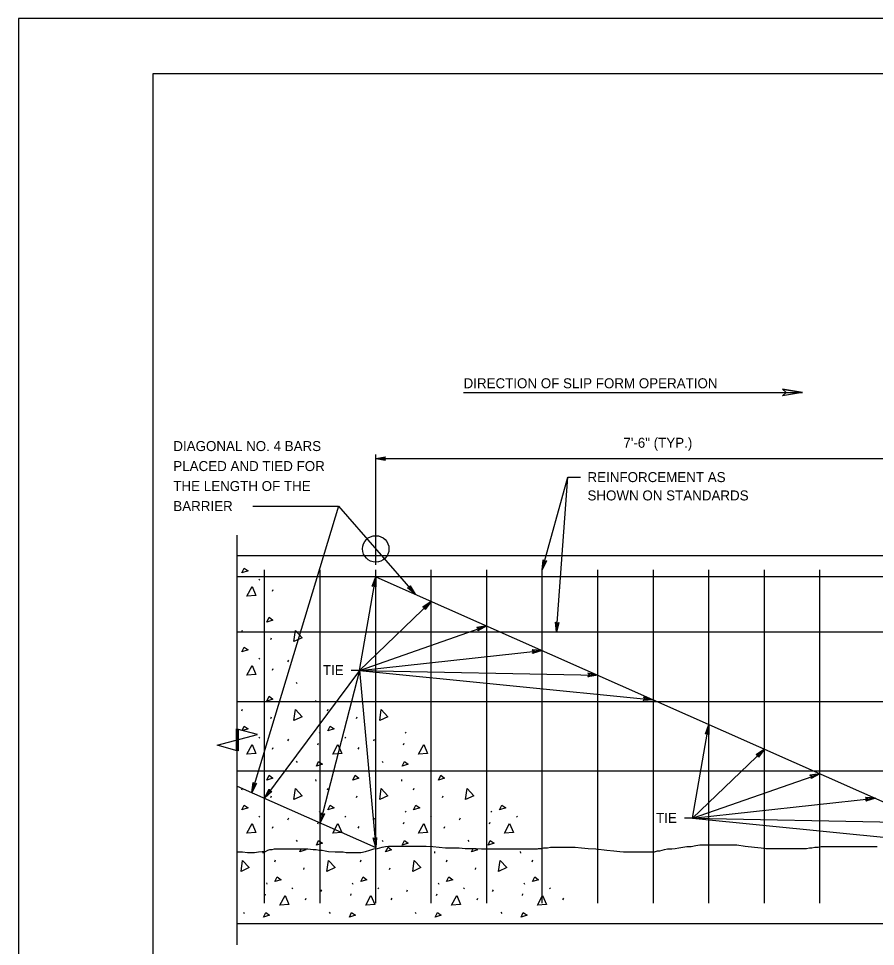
# Model space of a CAD drawing. Extents: x -113.6 to -105.1, y -201.8 to -190.8.
# Drawn here: x -113.61 to -108.47, y -196.35 to -190.78 of the extents above; entities that cross this region are included whole.
import ezdxf

# ---------------------------------------------------------------- set-up
doc = ezdxf.new("R2010")
doc.units = 0
for name, color, linetype in [('ANNO-DIMS', 7, 'Continuous'), ('ANNO-TEXT', 7, 'Continuous'), ('ANNO-WOUT', 7, 'Continuous'), ('BORD-LINE', 7, 'Continuous'), ('DETL-PATT', 7, 'Continuous'), ('Level 10', 7, 'Continuous'), ('Level 12', 7, 'Continuous'), ('SUBS-FOOT_P', 7, 'Continuous'), ('SUPR-PARA_P', 7, 'Continuous'), ('SUPR-RFRC', 7, 'Continuous'), ('USER-CLIP', 7, 'Continuous')]:
    doc.layers.add(name, color=color, linetype=linetype)

msp = doc.modelspace()

# ---------------------------------------------------------------- linework, layer by layer
at = {"layer": 'ANNO-DIMS'}
msp.add_lwpolyline([(-112.302, -195.1718), (-112.4227, -195.1394), (-112.1812, -195.0747), (-112.302, -195.0424)], dxfattribs=at)
msp.add_lwpolyline([(-112.2971, -195.1729), (-112.3062, -195.1706), (-112.3062, -195.0412), (-112.2971, -195.0437)], close=True, dxfattribs=at)
at = {"layer": 'ANNO-TEXT'}
msp.add_line((-112.302, -196.3362), (-112.302, -193.8779), dxfattribs=at)
at = {"layer": 'ANNO-WOUT'}
msp.add_circle((-111.4705, -193.9608), 0.0795, dxfattribs=at)
at = {"layer": 'BORD-LINE'}
msp.add_lwpolyline([(-112.8058, -191.1077), (-105.4316, -191.1077), (-105.4316, -201.4608), (-112.8058, -201.4608)], close=True, dxfattribs=at)
at = {"layer": 'DETL-PATT'}
for p, q in [((-112.1717, -194.1419), (-112.1665, -194.1483)), ((-112.0905, -194.214), (-112.0854, -194.2037)), ((-112.2747, -194.4588), (-112.2709, -194.4485)), ((-112.1008, -194.5051), (-112.0969, -194.4948)), ((-112.1717, -194.6159), (-112.1665, -194.6224)), ((-111.9978, -194.6378), (-111.9926, -194.6275)), ((-112.0905, -194.6881), (-112.0854, -194.6778)), ((-111.9475, -194.7615), (-111.9424, -194.7692)), ((-111.8316, -194.871), (-111.8303, -194.8813)), ((-112.2747, -194.9328), (-112.2709, -194.9225)), ((-111.7594, -194.9328), (-111.7556, -194.9225)), ((-112.1008, -194.9792), (-112.0969, -194.9689)), ((-111.5855, -194.9792), (-111.5816, -194.9689)), ((-111.8097, -195.0604), (-111.8058, -195.0668)), ((-111.2944, -195.0604), (-111.2905, -195.0668)), ((-112.1717, -195.09), (-112.1665, -195.0965)), ((-111.9978, -195.1119), (-111.9926, -195.1016)), ((-111.8187, -195.1364), (-111.8148, -195.1261)), ((-111.6564, -195.09), (-111.6512, -195.0965)), ((-111.4825, -195.1119), (-111.4773, -195.1016)), ((-111.3034, -195.1364), (-111.2995, -195.1261)), ((-112.0905, -195.1622), (-112.0854, -195.1519)), ((-111.5752, -195.1622), (-111.5701, -195.1519)), ((-111.9475, -195.2356), (-111.9424, -195.2433)), ((-111.4322, -195.2356), (-111.4271, -195.2433)), ((-111.8316, -195.3451), (-111.8303, -195.3554)), ((-111.3163, -195.3451), (-111.315, -195.3554)), ((-112.2747, -195.4069), (-112.2709, -195.3966)), ((-111.7594, -195.4069), (-111.7556, -195.3966)), ((-111.2441, -195.4069), (-111.2403, -195.3966)), ((-112.1008, -195.4533), (-112.0969, -195.443)), ((-111.5855, -195.4533), (-111.5816, -195.443)), ((-111.0702, -195.4533), (-111.0663, -195.443)), ((-112.1717, -195.5641), (-112.1665, -195.5705)), ((-111.9978, -195.586), (-111.9926, -195.5757)), ((-111.8097, -195.5345), (-111.8058, -195.5409)), ((-111.6564, -195.5641), (-111.6512, -195.5705)), ((-111.4825, -195.586), (-111.4773, -195.5757)), ((-111.2944, -195.5345), (-111.2905, -195.5409)), ((-111.1411, -195.5641), (-111.1359, -195.5705)), ((-110.9671, -195.586), (-110.962, -195.5757)), ((-110.7791, -195.5345), (-110.7752, -195.5409)), ((-110.6258, -195.5641), (-110.6206, -195.5705)), ((-112.0905, -195.6362), (-112.0854, -195.6259)), ((-111.8187, -195.6105), (-111.8148, -195.6002)), ((-111.5752, -195.6362), (-111.5701, -195.6259)), ((-111.3034, -195.6105), (-111.2995, -195.6002)), ((-111.0599, -195.6362), (-111.0547, -195.6259)), ((-110.7881, -195.6105), (-110.7842, -195.6002)), ((-111.9475, -195.7097), (-111.9424, -195.7174)), ((-111.4322, -195.7097), (-111.4271, -195.7174)), ((-110.9169, -195.7097), (-110.9118, -195.7174)), ((-112.149, -195.7761), (-112.1477, -195.7864)), ((-111.9261, -195.7786), (-111.9177, -195.7617)), ((-111.6329, -195.7829), (-111.6324, -195.7864)), ((-111.1184, -195.7761), (-111.1171, -195.7864)), ((-110.8955, -195.7786), (-110.8853, -195.7582)), ((-110.6031, -195.7761), (-110.6018, -195.7864)), ((-112.0769, -195.8379), (-112.073, -195.8276)), ((-111.5616, -195.8379), (-111.5577, -195.8276)), ((-111.0463, -195.8379), (-111.0424, -195.8276)), ((-110.531, -195.8379), (-110.5271, -195.8276)), ((-111.903, -195.8843), (-111.8991, -195.874)), ((-111.3877, -195.8843), (-111.3838, -195.874)), ((-110.8724, -195.8843), (-110.8685, -195.874)), ((-112.1271, -195.9654), (-112.1232, -195.9719)), ((-111.6118, -195.9654), (-111.6079, -195.9719)), ((-111.0965, -195.9654), (-111.0926, -195.9719)), ((-110.5812, -195.9654), (-110.5773, -195.9719)), ((-111.9738, -195.9951), (-111.9687, -196.0015)), ((-111.7999, -196.017), (-111.7947, -196.0067)), ((-111.4585, -195.9951), (-111.4534, -196.0015)), ((-111.2846, -196.017), (-111.2794, -196.0067)), ((-110.9432, -195.9951), (-110.9381, -196.0015)), ((-110.7693, -196.017), (-110.7641, -196.0067)), ((-110.4279, -195.9951), (-110.4228, -196.0015)), ((-112.1361, -196.0414), (-112.1323, -196.0311)), ((-111.8927, -196.0672), (-111.8875, -196.0569)), ((-111.6208, -196.0414), (-111.617, -196.0311)), ((-111.3774, -196.0672), (-111.3722, -196.0569)), ((-111.1055, -196.0414), (-111.1017, -196.0311)), ((-110.862, -196.0672), (-110.8569, -196.0569)), ((-110.5902, -196.0414), (-110.5864, -196.0311)), ((-110.3467, -196.0672), (-110.3416, -196.0569)), ((-112.265, -196.1406), (-112.2598, -196.1484)), ((-111.7497, -196.1406), (-111.7445, -196.1484)), ((-111.2344, -196.1406), (-111.2292, -196.1484)), ((-110.7191, -196.1406), (-110.7139, -196.1484))]:
    msp.add_line(p, q, dxfattribs=at)
for points in [[(-112.2734, -194.1045), (-112.2593, -194.0762), (-112.2361, -194.0929), (-112.2734, -194.1045)], [(-112.2438, -194.2449), (-112.2129, -194.1869), (-112.1897, -194.2411), (-112.2438, -194.2449)], [(-112.124, -194.3995), (-112.1098, -194.3712), (-112.0879, -194.3879), (-112.124, -194.3995)], [(-111.9617, -194.5167), (-111.9527, -194.451), (-111.9127, -194.4936), (-111.9617, -194.5167)], [(-112.2734, -194.5786), (-112.2593, -194.5502), (-112.2361, -194.567), (-112.2734, -194.5786)], [(-112.2438, -194.719), (-112.2129, -194.661), (-112.1897, -194.7151), (-112.2438, -194.719)], [(-112.124, -194.8736), (-112.1098, -194.8452), (-112.0879, -194.862), (-112.124, -194.8736)], [(-111.9617, -194.9908), (-111.9527, -194.9251), (-111.9127, -194.9676), (-111.9617, -194.9908)], [(-111.4464, -194.9908), (-111.4374, -194.9251), (-111.3974, -194.9676), (-111.4464, -194.9908)], [(-112.2723, -195.0503), (-112.2593, -195.0243), (-112.2361, -195.0411), (-112.2688, -195.0512)], [(-111.7581, -195.0527), (-111.744, -195.0243), (-111.7208, -195.0411), (-111.7581, -195.0527)], [(-112.2438, -195.1931), (-112.2129, -195.1351), (-112.1897, -195.1892), (-112.2438, -195.1931)], [(-111.7285, -195.1931), (-111.6976, -195.1351), (-111.6744, -195.1892), (-111.7285, -195.1931)], [(-111.2132, -195.1931), (-111.1823, -195.1351), (-111.1591, -195.1892), (-111.2132, -195.1931)], [(-111.8264, -195.2652), (-111.8135, -195.2369), (-111.7903, -195.2536), (-111.8264, -195.2652)], [(-111.3111, -195.2652), (-111.2982, -195.2369), (-111.275, -195.2536), (-111.3111, -195.2652)], [(-112.124, -195.3477), (-112.1098, -195.3193), (-112.0879, -195.3361), (-112.124, -195.3477)], [(-111.6087, -195.3477), (-111.5945, -195.3193), (-111.5726, -195.3361), (-111.6087, -195.3477)], [(-111.0934, -195.3477), (-111.0792, -195.3193), (-111.0573, -195.3361), (-111.0934, -195.3477)], [(-111.9617, -195.4649), (-111.9527, -195.3992), (-111.9127, -195.4417), (-111.9617, -195.4649)], [(-111.4464, -195.4649), (-111.4374, -195.3992), (-111.3974, -195.4417), (-111.4464, -195.4649)], [(-110.9311, -195.4649), (-110.9221, -195.3992), (-110.8821, -195.4417), (-110.9311, -195.4649)], [(-112.2734, -195.5267), (-112.2593, -195.4984), (-112.2361, -195.5151), (-112.2734, -195.5267)], [(-111.7581, -195.5267), (-111.744, -195.4984), (-111.7208, -195.5151), (-111.7581, -195.5267)], [(-111.2428, -195.5267), (-111.2287, -195.4984), (-111.2055, -195.5151), (-111.2428, -195.5267)], [(-110.7275, -195.5267), (-110.7134, -195.4984), (-110.6902, -195.5151), (-110.7275, -195.5267)], [(-112.2438, -195.6672), (-112.2129, -195.6092), (-112.1897, -195.6633), (-112.2438, -195.6672)], [(-111.7285, -195.6672), (-111.6976, -195.6092), (-111.6744, -195.6633), (-111.7285, -195.6672)], [(-111.2132, -195.6672), (-111.1823, -195.6092), (-111.1591, -195.6633), (-111.2132, -195.6672)], [(-110.6979, -195.6672), (-110.667, -195.6092), (-110.6438, -195.6633), (-110.6979, -195.6672)], [(-111.8264, -195.7393), (-111.8135, -195.711), (-111.7903, -195.7277), (-111.8264, -195.7393)], [(-111.3111, -195.7393), (-111.2982, -195.711), (-111.275, -195.7277), (-111.3111, -195.7393)], [(-110.7958, -195.7393), (-110.7829, -195.711), (-110.7597, -195.7277), (-110.7958, -195.7393)], [(-111.897, -195.7617), (-111.8901, -195.767), (-111.9261, -195.7786)], [(-111.4108, -195.7786), (-111.3967, -195.7503), (-111.3748, -195.767), (-111.4108, -195.7786)], [(-110.8711, -195.7582), (-110.8595, -195.767), (-110.8955, -195.7786)], [(-112.2791, -195.8959), (-112.2701, -195.8302), (-112.2302, -195.8727), (-112.2791, -195.8959)], [(-111.7638, -195.8959), (-111.7548, -195.8302), (-111.7149, -195.8727), (-111.7638, -195.8959)], [(-111.2485, -195.8959), (-111.2395, -195.8302), (-111.1996, -195.8727), (-111.2485, -195.8959)], [(-110.7332, -195.8959), (-110.7242, -195.8302), (-110.6843, -195.8727), (-110.7332, -195.8959)], [(-112.0756, -195.9577), (-112.0614, -195.9294), (-112.0382, -195.9461), (-112.0756, -195.9577)], [(-111.5603, -195.9577), (-111.5461, -195.9294), (-111.5229, -195.9461), (-111.5603, -195.9577)], [(-111.045, -195.9577), (-111.0308, -195.9294), (-111.0076, -195.9461), (-111.045, -195.9577)], [(-110.5297, -195.9577), (-110.5155, -195.9294), (-110.4923, -195.9461), (-110.5297, -195.9577)], [(-112.046, -196.0981), (-112.015, -196.0402), (-111.9918, -196.0943), (-112.046, -196.0981)], [(-111.5307, -196.0981), (-111.4997, -196.0402), (-111.4765, -196.0943), (-111.5307, -196.0981)], [(-111.0154, -196.0981), (-110.9844, -196.0402), (-110.9612, -196.0943), (-111.0154, -196.0981)], [(-110.5, -196.0981), (-110.4691, -196.0402), (-110.4459, -196.0943), (-110.5, -196.0981)], [(-112.1439, -196.1703), (-112.131, -196.1419), (-112.1078, -196.1587), (-112.1439, -196.1703)], [(-111.6286, -196.1703), (-111.6157, -196.1419), (-111.5925, -196.1587), (-111.6286, -196.1703)], [(-111.1133, -196.1703), (-111.1004, -196.1419), (-111.0772, -196.1587), (-111.1133, -196.1703)], [(-110.598, -196.1703), (-110.5851, -196.1419), (-110.5619, -196.1587), (-110.598, -196.1703)]]:
    msp.add_lwpolyline(points, dxfattribs=at)
at = {"layer": 'Level 10'}
for p, q in [((-108.909, -193.022), (-109.0284, -193.001)), ((-109.0284, -193.001), (-109.0057, -193.022)), ((-110.9431, -193.022), (-108.909, -193.022)), ((-108.909, -193.022), (-109.0284, -193.043)), ((-109.0057, -193.022), (-109.0284, -193.043)), ((-111.4705, -194.0567), (-111.4705, -193.3935)), ((-111.4705, -193.4185), (-111.411, -193.408)), ((-111.4705, -193.4185), (-107.8038, -193.4185)), ((-111.4705, -193.4185), (-111.411, -193.429)), ((-111.4222, -193.4185), (-111.411, -193.408)), ((-111.411, -193.429), (-111.4222, -193.4185)), ((-110.4705, -194.0862), (-110.3178, -193.5299)), ((-110.3857, -194.4612), (-110.3178, -193.5299)), ((-110.3178, -193.5299), (-110.2408, -193.5299)), ((-111.6944, -193.7042), (-112.214, -195.4234)), ((-112.2089, -193.7042), (-111.6944, -193.7042)), ((-111.6944, -193.7042), (-111.2329, -194.2332)), ((-110.4705, -194.0862), (-110.465, -194.026)), ((-110.4705, -194.0862), (-110.4447, -194.0317)), ((-110.4577, -194.0396), (-110.465, -194.026)), ((-110.4447, -194.0317), (-110.4577, -194.0396)), ((-111.5687, -194.6909), (-111.4705, -194.1279)), ((-111.4705, -194.1279), (-111.491, -194.1847)), ((-111.4705, -194.1279), (-111.4704, -194.1883)), ((-111.491, -194.1847), (-111.4788, -194.1754)), ((-111.4788, -194.1754), (-111.4704, -194.1883)), ((-111.2641, -194.1815), (-111.2646, -194.1968)), ((-111.2329, -194.2332), (-111.2641, -194.1815)), ((-111.2329, -194.2332), (-111.2799, -194.1951)), ((-111.2646, -194.1968), (-111.2799, -194.1951)), ((-111.5687, -194.6909), (-111.1372, -194.2756)), ((-111.1372, -194.2756), (-111.1873, -194.3094)), ((-111.1372, -194.2756), (-111.1727, -194.3245)), ((-111.1873, -194.3094), (-111.172, -194.3091)), ((-111.172, -194.3091), (-111.1727, -194.3245)), ((-110.3857, -194.4612), (-110.392, -194.401)), ((-110.3821, -194.413), (-110.392, -194.401)), ((-110.3857, -194.4612), (-110.3709, -194.4025)), ((-110.3709, -194.4025), (-110.3821, -194.413)), ((-111.5687, -194.6909), (-110.8039, -194.4233)), ((-110.8039, -194.4233), (-110.8635, -194.4331)), ((-110.8635, -194.4331), (-110.8494, -194.4393)), ((-110.8039, -194.4233), (-110.8565, -194.4529)), ((-110.8494, -194.4393), (-110.8565, -194.4529)), ((-111.5687, -194.6909), (-110.4705, -194.5711)), ((-110.4705, -194.5711), (-110.5308, -194.5672)), ((-110.5308, -194.5672), (-110.5185, -194.5763)), ((-110.4705, -194.5711), (-110.5285, -194.588)), ((-110.5185, -194.5763), (-110.5285, -194.588)), ((-111.5687, -194.6909), (-112.1372, -195.4574)), ((-111.5687, -194.6909), (-111.8039, -195.6052)), ((-111.5687, -194.6909), (-111.6171, -194.6909)), ((-111.5687, -194.6909), (-110.1372, -194.7188)), ((-111.5687, -194.6909), (-109.8038, -194.8665)), ((-111.5687, -194.6909), (-111.4705, -195.7529)), ((-110.1854, -194.7179), (-110.1969, -194.7282)), ((-110.1372, -194.7188), (-110.1969, -194.7282)), ((-110.1372, -194.7188), (-110.1965, -194.7072)), ((-110.1965, -194.7072), (-110.1854, -194.7179)), ((-109.8038, -194.8665), (-109.862, -194.8503)), ((-109.862, -194.8503), (-109.8519, -194.8617)), ((-109.8519, -194.8617), (-109.8641, -194.8711)), ((-109.8038, -194.8665), (-109.8641, -194.8711)), ((-109.5686, -195.5773), (-109.4705, -195.0143)), ((-109.4705, -195.0143), (-109.491, -195.0711)), ((-109.4705, -195.0143), (-109.4703, -195.0747)), ((-109.491, -195.0711), (-109.4788, -195.0618)), ((-109.4788, -195.0618), (-109.4703, -195.0747)), ((-109.5686, -195.5773), (-109.1372, -195.162)), ((-109.1372, -195.162), (-109.1873, -195.1957)), ((-109.1372, -195.162), (-109.1727, -195.2108)), ((-109.1873, -195.1957), (-109.1719, -195.1955)), ((-109.1719, -195.1955), (-109.1727, -195.2108)), ((-109.5686, -195.5773), (-108.8038, -195.3097)), ((-108.8038, -195.3097), (-108.8635, -195.3195)), ((-108.8635, -195.3195), (-108.8494, -195.3257)), ((-108.8038, -195.3097), (-108.8565, -195.3393)), ((-108.8494, -195.3257), (-108.8565, -195.3393)), ((-112.214, -195.4234), (-112.2068, -195.3634)), ((-112.214, -195.4234), (-112.1868, -195.3695)), ((-112.2, -195.3772), (-112.2068, -195.3634)), ((-112.1868, -195.3695), (-112.2, -195.3772)), ((-112.1372, -195.4574), (-112.1102, -195.4034)), ((-112.1084, -195.4187), (-112.1102, -195.4034)), ((-112.1372, -195.4574), (-112.0934, -195.4158)), ((-112.0934, -195.4158), (-112.1084, -195.4187)), ((-109.5686, -195.5773), (-108.4705, -195.4574)), ((-108.4705, -195.4574), (-108.5308, -195.4535)), ((-108.5308, -195.4535), (-108.5185, -195.4627)), ((-108.4705, -195.4574), (-108.5285, -195.4744)), ((-108.5185, -195.4627), (-108.5285, -195.4744)), ((-111.8039, -195.6052), (-111.7992, -195.5449)), ((-111.8039, -195.6052), (-111.7789, -195.5501)), ((-111.7918, -195.5584), (-111.7992, -195.5449)), ((-111.7789, -195.5501), (-111.7918, -195.5584)), ((-109.5686, -195.5773), (-109.6171, -195.5773)), ((-109.5686, -195.5773), (-108.1372, -195.6052)), ((-109.5686, -195.5773), (-107.8038, -195.7529)), ((-111.4705, -195.7529), (-111.4865, -195.6946)), ((-111.475, -195.7048), (-111.4865, -195.6946)), ((-111.4656, -195.6927), (-111.475, -195.7048)), ((-111.4705, -195.7529), (-111.4656, -195.6927))]:
    msp.add_line(p, q, dxfattribs=at)
for points in [[(-109.0284, -193.001), (-108.909, -193.022), (-109.0284, -193.043), (-109.0057, -193.022)], [(-111.411, -193.429), (-111.4705, -193.4185), (-111.411, -193.408), (-111.4222, -193.4185)], [(-110.4447, -194.0317), (-110.4705, -194.0862), (-110.465, -194.026), (-110.4577, -194.0396)], [(-111.491, -194.1847), (-111.4705, -194.1279), (-111.4704, -194.1883), (-111.4788, -194.1754)], [(-111.2641, -194.1815), (-111.2329, -194.2332), (-111.2799, -194.1951), (-111.2646, -194.1968)], [(-111.1873, -194.3094), (-111.1372, -194.2756), (-111.1727, -194.3245), (-111.172, -194.3091)], [(-110.3709, -194.4025), (-110.3857, -194.4612), (-110.392, -194.401), (-110.3821, -194.413)], [(-110.8635, -194.4331), (-110.8039, -194.4233), (-110.8565, -194.4529), (-110.8494, -194.4393)], [(-110.5308, -194.5672), (-110.4705, -194.5711), (-110.5285, -194.588), (-110.5185, -194.5763)], [(-110.1965, -194.7072), (-110.1372, -194.7188), (-110.1969, -194.7282), (-110.1854, -194.7179)], [(-109.862, -194.8503), (-109.8038, -194.8665), (-109.8641, -194.8711), (-109.8519, -194.8617)], [(-109.491, -195.0711), (-109.4705, -195.0143), (-109.4703, -195.0747), (-109.4788, -195.0618)], [(-109.1873, -195.1957), (-109.1372, -195.162), (-109.1727, -195.2108), (-109.1719, -195.1955)], [(-108.8635, -195.3195), (-108.8038, -195.3097), (-108.8565, -195.3393), (-108.8494, -195.3257)], [(-112.1868, -195.3695), (-112.214, -195.4234), (-112.2068, -195.3634), (-112.2, -195.3772)], [(-112.0934, -195.4158), (-112.1372, -195.4574), (-112.1102, -195.4034), (-112.1084, -195.4187)], [(-108.5308, -195.4535), (-108.4705, -195.4574), (-108.5285, -195.4744), (-108.5185, -195.4627)], [(-111.7789, -195.5501), (-111.8039, -195.6052), (-111.7992, -195.5449), (-111.7918, -195.5584)], [(-111.4656, -195.6927), (-111.4705, -195.7529), (-111.4865, -195.6946), (-111.475, -195.7048)]]:
    msp.add_lwpolyline(points, close=True, dxfattribs=at)
at = {"layer": 'SUBS-FOOT_P'}
msp.add_line((-107.7205, -196.2112), (-112.302, -196.2112), dxfattribs=at)
msp.add_lwpolyline([(-112.302, -195.7794), (-112.2977, -195.7794), (-112.2695, -195.7794), (-112.2412, -195.7829), (-112.1988, -195.7829), (-112.1741, -195.7794), (-112.1529, -195.7759), (-112.1317, -195.7759), (-112.1175, -195.7688), (-112.1069, -195.7653), (-112.0928, -195.7653), (-112.0787, -195.7617), (-112.061, -195.7617), (-112.0434, -195.7617), (-112.0222, -195.7617), (-112.008, -195.7617), (-111.9762, -195.7617), (-111.955, -195.7617), (-111.9338, -195.7617), (-111.902, -195.7617), (-111.8773, -195.7617), (-111.8455, -195.7653), (-111.8278, -195.7653), (-111.8102, -195.7688), (-111.7925, -195.7688), (-111.7748, -195.7723), (-111.7536, -195.7759), (-111.7148, -195.7794), (-111.69, -195.7794), (-111.6653, -195.7794), (-111.6476, -195.7829), (-111.63, -195.7829), (-111.6123, -195.7829), (-111.5946, -195.7829), (-111.577, -195.7829), (-111.5593, -195.7829), (-111.5311, -195.7759), (-111.5063, -195.7688), (-111.4816, -195.7617), (-111.4604, -195.7582), (-111.4321, -195.7511), (-111.4109, -195.7476), (-111.3933, -195.744), (-111.3756, -195.744), (-111.3473, -195.744), (-111.3226, -195.744), (-111.2873, -195.744), (-111.259, -195.744), (-111.2343, -195.744), (-111.2095, -195.744), (-111.1883, -195.744), (-111.1671, -195.744), (-111.1283, -195.7476), (-111.0894, -195.7511), (-111.0506, -195.7546), (-111.0082, -195.7546), (-110.9693, -195.7546), (-110.934, -195.7582), (-110.9022, -195.7582), (-110.8668, -195.7582), (-110.835, -195.7617), (-110.7962, -195.7617), (-110.7573, -195.7617), (-110.7078, -195.7617), (-110.6442, -195.7617), (-110.5912, -195.7617), (-110.5524, -195.7617), (-110.5312, -195.7617), (-110.51, -195.7617), (-110.4994, -195.7617), (-110.4923, -195.7582), (-110.4853, -195.7582), (-110.4747, -195.7582), (-110.4605, -195.7546), (-110.4393, -195.7546), (-110.4217, -195.7511), (-110.4005, -195.7511), (-110.3828, -195.7511), (-110.3687, -195.7511), (-110.351, -195.7511), (-110.3369, -195.7511), (-110.3192, -195.7511), (-110.298, -195.7511), (-110.2733, -195.7511), (-110.2344, -195.7546), (-110.1955, -195.7582), (-110.1496, -195.7617), (-110.0825, -195.7688), (-110.0401, -195.7723), (-110.0048, -195.7759), (-109.9836, -195.7794), (-109.9694, -195.7794), (-109.9553, -195.7794), (-109.9412, -195.7794), (-109.9306, -195.7794), (-109.9094, -195.7794), (-109.8882, -195.7794), (-109.8634, -195.7794), (-109.8246, -195.7794), (-109.7963, -195.7794), (-109.7786, -195.7723), (-109.7645, -195.7723), (-109.7504, -195.7688), (-109.7362, -195.7653), (-109.7186, -195.7617), (-109.6938, -195.7617), (-109.6726, -195.7582), (-109.6514, -195.7546), (-109.6267, -195.7511), (-109.602, -195.7476), (-109.5772, -195.7476), (-109.549, -195.7405), (-109.5243, -195.737), (-109.5031, -195.737), (-109.4854, -195.737), (-109.4642, -195.737), (-109.4465, -195.737), (-109.4289, -195.737), (-109.4077, -195.737), (-109.3794, -195.737), (-109.3441, -195.737), (-109.3017, -195.737), (-109.2522, -195.744), (-109.1957, -195.7511), (-109.1568, -195.7546), (-109.1285, -195.7582), (-109.1144, -195.7582), (-109.1038, -195.7582), (-109.0932, -195.7582), (-109.0861, -195.7582), (-109.0791, -195.7582), (-109.0685, -195.7582), (-109.0508, -195.7582), (-109.0332, -195.7582), (-108.9943, -195.7582), (-108.9696, -195.7582), (-108.9519, -195.7582), (-108.9413, -195.7582), (-108.9272, -195.7582), (-108.906, -195.7582), (-108.8848, -195.7582), (-108.8671, -195.7546), (-108.853, -195.7546), (-108.8353, -195.7511), (-108.8141, -195.7511), (-108.7964, -195.7476), (-108.7682, -195.7476), (-108.7576, -195.7476), (-108.7399, -195.7476), (-108.7152, -195.7476), (-108.6904, -195.7476), (-108.6551, -195.7476), (-108.6304, -195.7476), (-108.6021, -195.7476), (-108.5632, -195.7476), (-108.5385, -195.7476), (-108.5173, -195.7476), (-108.5067, -195.7476), (-108.4926, -195.7476), (-108.4855, -195.7476), (-108.4714, -195.7476), (-108.4608, -195.7476)], dxfattribs=at)
at = {"layer": 'SUPR-PARA_P'}
msp.add_line((-107.7205, -194.0029), (-112.302, -194.0029), dxfattribs=at)
at = {"layer": 'SUPR-RFRC'}
for p, q in [((-107.8038, -194.1279), (-112.302, -194.1279)), ((-112.1372, -196.0862), (-112.1372, -194.0862)), ((-111.8039, -196.0862), (-111.8039, -194.0862)), ((-111.4705, -196.0862), (-111.4705, -194.0862)), ((-111.4705, -194.1279), (-107.8038, -195.7529)), ((-111.1372, -196.0862), (-111.1372, -194.0862)), ((-110.8039, -196.0862), (-110.8039, -194.0862)), ((-110.4705, -196.0862), (-110.4705, -194.0862)), ((-110.1372, -196.0862), (-110.1372, -194.0862)), ((-109.8038, -196.0862), (-109.8038, -194.0862)), ((-109.4705, -196.0862), (-109.4705, -194.0862)), ((-109.1372, -196.0862), (-109.1372, -194.0862)), ((-108.8038, -196.0862), (-108.8038, -194.0862)), ((-107.8038, -194.4612), (-112.302, -194.4612)), ((-107.8038, -194.8779), (-112.302, -194.8779)), ((-107.8038, -195.2946), (-112.302, -195.2946)), ((-112.302, -195.3844), (-111.4705, -195.7529))]:
    msp.add_line(p, q, dxfattribs=at)
at = {"layer": 'USER-CLIP'}
msp.add_lwpolyline([(-105.1147, -190.7777), (-113.6147, -190.7777), (-113.6147, -201.7777), (-105.1147, -201.7777)], close=True, dxfattribs=at)

# ---------------------------------------------------------------- texts
at = {"layer": 'Level 12'}
for s, height, p in [('DIRECTION OF SLIP FORM OPERATION', 0.06, (-110.9431, -192.9966)), ('7\'-6" (TYP.)', 0.060001, (-109.9839, -193.3537)), ('DIAGONAL NO. 4 BARS', 0.060001, (-112.6856, -193.3735)), ('PLACED AND TIED FOR', 0.060001, (-112.6856, -193.4935)), ('REINFORCEMENT AS', 0.060001, (-110.1992, -193.5598)), ('THE LENGTH OF THE', 0.060001, (-112.6856, -193.6135)), ('SHOWN ON STANDARDS', 0.060001, (-110.1992, -193.6698)), ('BARRIER', 0.06, (-112.6856, -193.7336)), ('TIE', 0.06, (-111.7874, -194.7184)), ('TIE', 0.06, (-109.7874, -195.6048))]:
    msp.add_text(s, height=height, dxfattribs=at).set_placement(p)

doc.saveas('drawing.dxf')
